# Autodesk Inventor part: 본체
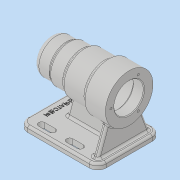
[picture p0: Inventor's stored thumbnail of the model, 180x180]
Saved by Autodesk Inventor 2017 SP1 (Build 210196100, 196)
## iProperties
Part Number: 본체
Material: 일반
Document SubType Name: Modeling
Designer: MRC
Density: 1 g/cm^3
Appearance: 기본값
Author: MRC
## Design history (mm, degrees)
sketch "스케치1"
  geometry: L1 (0, 0)-(-112, 0); L2 (-112, 0)-(-112, 25); L3 (-112, 25)-(-88, 25); L4 (-88, 25)-(-88, 27); L5 (-88, 27)-(-66, 27); L6 (-66, 27)-(-66, 30); L7 (-66, 30)-(-32, 30); L8 (-32, 30)-(-32, 34); L9 (-32, 34)-(0, 34); L10 (0, 34)-(0, 21); L11 (0, 21)-(-15, 21); L12 (-15, 21)-(-15, 24); L13 (-15, 24)-(-69, 24); L14 (-69, 24)-(-69, 21); L15 (-69, 21)-(-81, 21); L16 (-81, 21)-(-81, 17.5); L17 (-81, 17.5)-(-99, 17.5); L18 (-99, 17.5)-(-99, 16); L19 (-99, 16)-(-103, 16); L20 (-103, 16)-(-103, 10.5); L21 (-103, 10.5)-(-106, 10.5); L22 (-106, 10.5)-(-106, 0); 1 further point
  constraints: 44 end point, 19 perpendicular, 2 horizontal, 1 coincident, 1 collinear, 1 point on line, 1 vertical, 1 vertical alignment
  dimensions: "d0" = 112 distance of L1.start L1.end; "d1" = 50 diameter of L3 L1; "d2" = 54 diameter of L5 L1; "d3" = 60 diameter of L7 L1; "d4" = 68 diameter of L9 L1; "d6" = 42 diameter of L11 L1; "d7" = 48 diameter of L13 L1; "d8" = 35 diameter of L17 L1; "d9" = 32 diameter of L19 L1; "d10" = 21 diameter of L21 L1; "d11" = 15 distance of L10.end L11.end; "d12" = 54 distance of L12.end L13.end; "d13" = 12 distance of L14.end L15.end; "d14" = 18 distance of L16.end L17.end; "d15" = 4 distance of L18.end L19.end; "d16" = 3 distance of L20.end L21.end; "d17" = 24 distance of L2.end L3.end; "d18" = 46 distance between parallel lines of L6 L2; "d19" = 80 distance between parallel lines of L8 L2
revolve "회전1" sketch "스케치1" stored, may be unused: angle "d20" = 90 deg
fillet "모깎기1" dims "d21" = 8
fillet "모깎기2" dims "d22" = 3
fillet "모깎기3" dims "d23" = 3
chamfer "모따기1" distance "d24" = 1; stored, may be unused: second distance "d25" = 2, angle "d26" = 45 deg
fillet "모깎기4" dims "d27" = 0.3
fillet "모깎기5" dims "d28" = 3
fillet "모깎기6" dims "d29" = 3
sketch "스케치2"
  geometry: L1 (-112, -62)-(0, -62); L2 (0, -62)-(0, -70); L3 (0, -70)-(-112, -70); L4 (-112, -70)-(-112, -62); 1 further point
  constraints: 8 end point, 2 parallel, 1 horizontal, 1 perpendicular, 1 vertical alignment
  dimensions: "d30" = 112 distance of L2.end L3.end; "d31" = 8 distance of L1.end L2.end; "d32" = 70 distance from line of L3 point (0, 0)
extrude "돌출1" join sketch "스케치2" stored distance "d33" = 90; taper "d34" = 0 deg
fillet "모깎기7" dims "d35" = 12
sketch "스케치3"
  geometry: L1 (100, 12)-(100, 78) reference; L2 (84, 49)-(92, 49); L3 (92, 49)-(92, 41); L4 (92, 41)-(84, 41); L5 (84, 41)-(84, 49); L6 (84, 49)-(92, 41); L7 (92, 49)-(84, 41); 4 further points
  constraints: 12 end point, 4 midpoint, 2 parallel, 1 horizontal, 1 horizontal alignment, 1 perpendicular
  dimensions: "d36" = 8 distance of L3.end L4.end; "d37" = 8 distance of L2.end L3.end; "d38" = 8 distance between parallel lines of L1 L3
extrude "돌출2" join sketch "스케치3" stored distance "d39" = 0; taper "d40" = 0 deg
sketch "스케치4"
  geometry: L1 (-85, -62)-(-78.072, -36.145); L2 (-100, -62)-(-12, -62) reference; L3 (0, -62)-(0, -70) reference; 1 further point
  constraints: 2 end point, 1 point on line
  dimensions: "d41" = 105 deg angle of L1 L2; "d42" = 85 distance from line of L1.start L3
feature "리브1" sketch "스케치4" dims "d43" = 1, "d44" = 8, "d45" = 0, "d46" = 0, "d47" = 1, "d48" = 1
sketch "스케치5"
  geometry: L1 (29.05, 32.832)-(41, 0); L2 (37, 0)-(49, 0) reference; L3 (49, -8)-(49, 0) reference
  constraints: 2 end point, 1 point on line
  dimensions: "d49" = 8 distance from line of L1.end L3; "d51" = 110 deg angle of L1 L2
feature "리브2" sketch "스케치5" dims "d52" = 1, "d53" = 8, "d54" = 0, "d55" = 0, "d56" = 1, "d57" = 1
sketch "스케치6"
  geometry: L1 (-12, -12)-(-12, -78) reference; L2 (8, -78)-(23, -78); L3 (8, -82.5)-(23, -82.5); L4 (23, -73.5)-(8, -73.5); A1 r 4.5 centre (8, -78) between (8, -73.5) and (8, -82.5); A2 r 4.5 centre (23, -78) between (23, -82.5) and (23, -73.5); 2 further points
  constraints: 8 end point, 4 point on circle, 4 tangent, 2 centre point, 1 horizontal, 1 midpoint, 1 parallel
  dimensions: "d58" = 15 distance of L2.start L2.end; "d59" = 9 distance between parallel lines of L3 L4; "d60" = 33 distance from line of L2 point (100, -45); "d61" = 20 distance from line of L2.start L1
extrude "돌출3" cut sketch "스케치6" stored distance "d62" = 90; taper "d63" = 0 deg
fillet "모깎기8" dims "d70" = 3
fillet "모깎기9" dims "d71" = 3
sketch "스케치7"
  geometry: C1 r 22 at (0, 0) reference; 1 further point
  constraints: 1 horizontal alignment
  dimensions: "d72" = 26 distance of point (-26, 0) C1.centre
hole "구멍1" sketch "스케치7" at (-26, 0) diameter "d73" = 3.242; stored, may be unused: countersink angle "d77" = 90 deg, drill point angle "d79" = 118 deg; dims "d74" = 8, "d75" = 4, "d76" = 2, "d78" = 11
sketch "스케치8"
  geometry: L1 (-12, -9)-(-12, -75) reference; 2 further points
  constraints: 1 horizontal alignment, 1 other
  dimensions: "d83" = 12 distance from line of point (0, -42) L1
feature "엠보싱1" sketch "스케치8" dims "d0" = 112, "d1" = 50, "d2" = 54, "d3" = 60, "d4" = 68, "d6" = 42, "d7" = 48, "d8" = 35, "d9" = 32, "d10" = 21, "d11" = 15, "d12" = 54, "d13" = 12, "d14" = 18, "d15" = 4, "d16" = 3, "d17" = 24, "d18" = 46, "d19" = 80, "d84" = 0.5, "d85" = 0
node "솔리드1"
mirror "미러1"
pattern_linear "직사각형 패턴1" dims "d66" = 40, "d69" = 66
pattern_circular "원형 패턴1" dims angle "d81" = 360 deg
